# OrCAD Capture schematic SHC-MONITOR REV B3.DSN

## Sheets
1 01 Title Page: title: Monitor; rev: C; company: Freescale Semiconductor; note: SCH-MONITOR PDF: SPF-MONITOR; note: 6501 William Cannon Drive West; note: Austin, TX 78735-8598
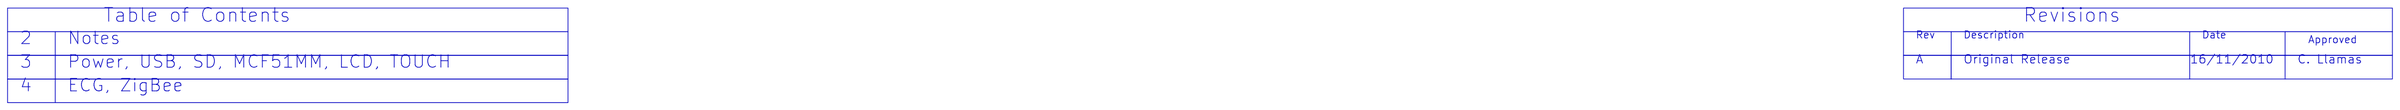
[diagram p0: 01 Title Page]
2 02 Notes: note: SCH-XXXXX PDF: SPF-XXXXX
3 03 Power, MCF51MM, USB, SD, LCD: size C; note: SCH-XXXXX PDF: SPF-XXXXX
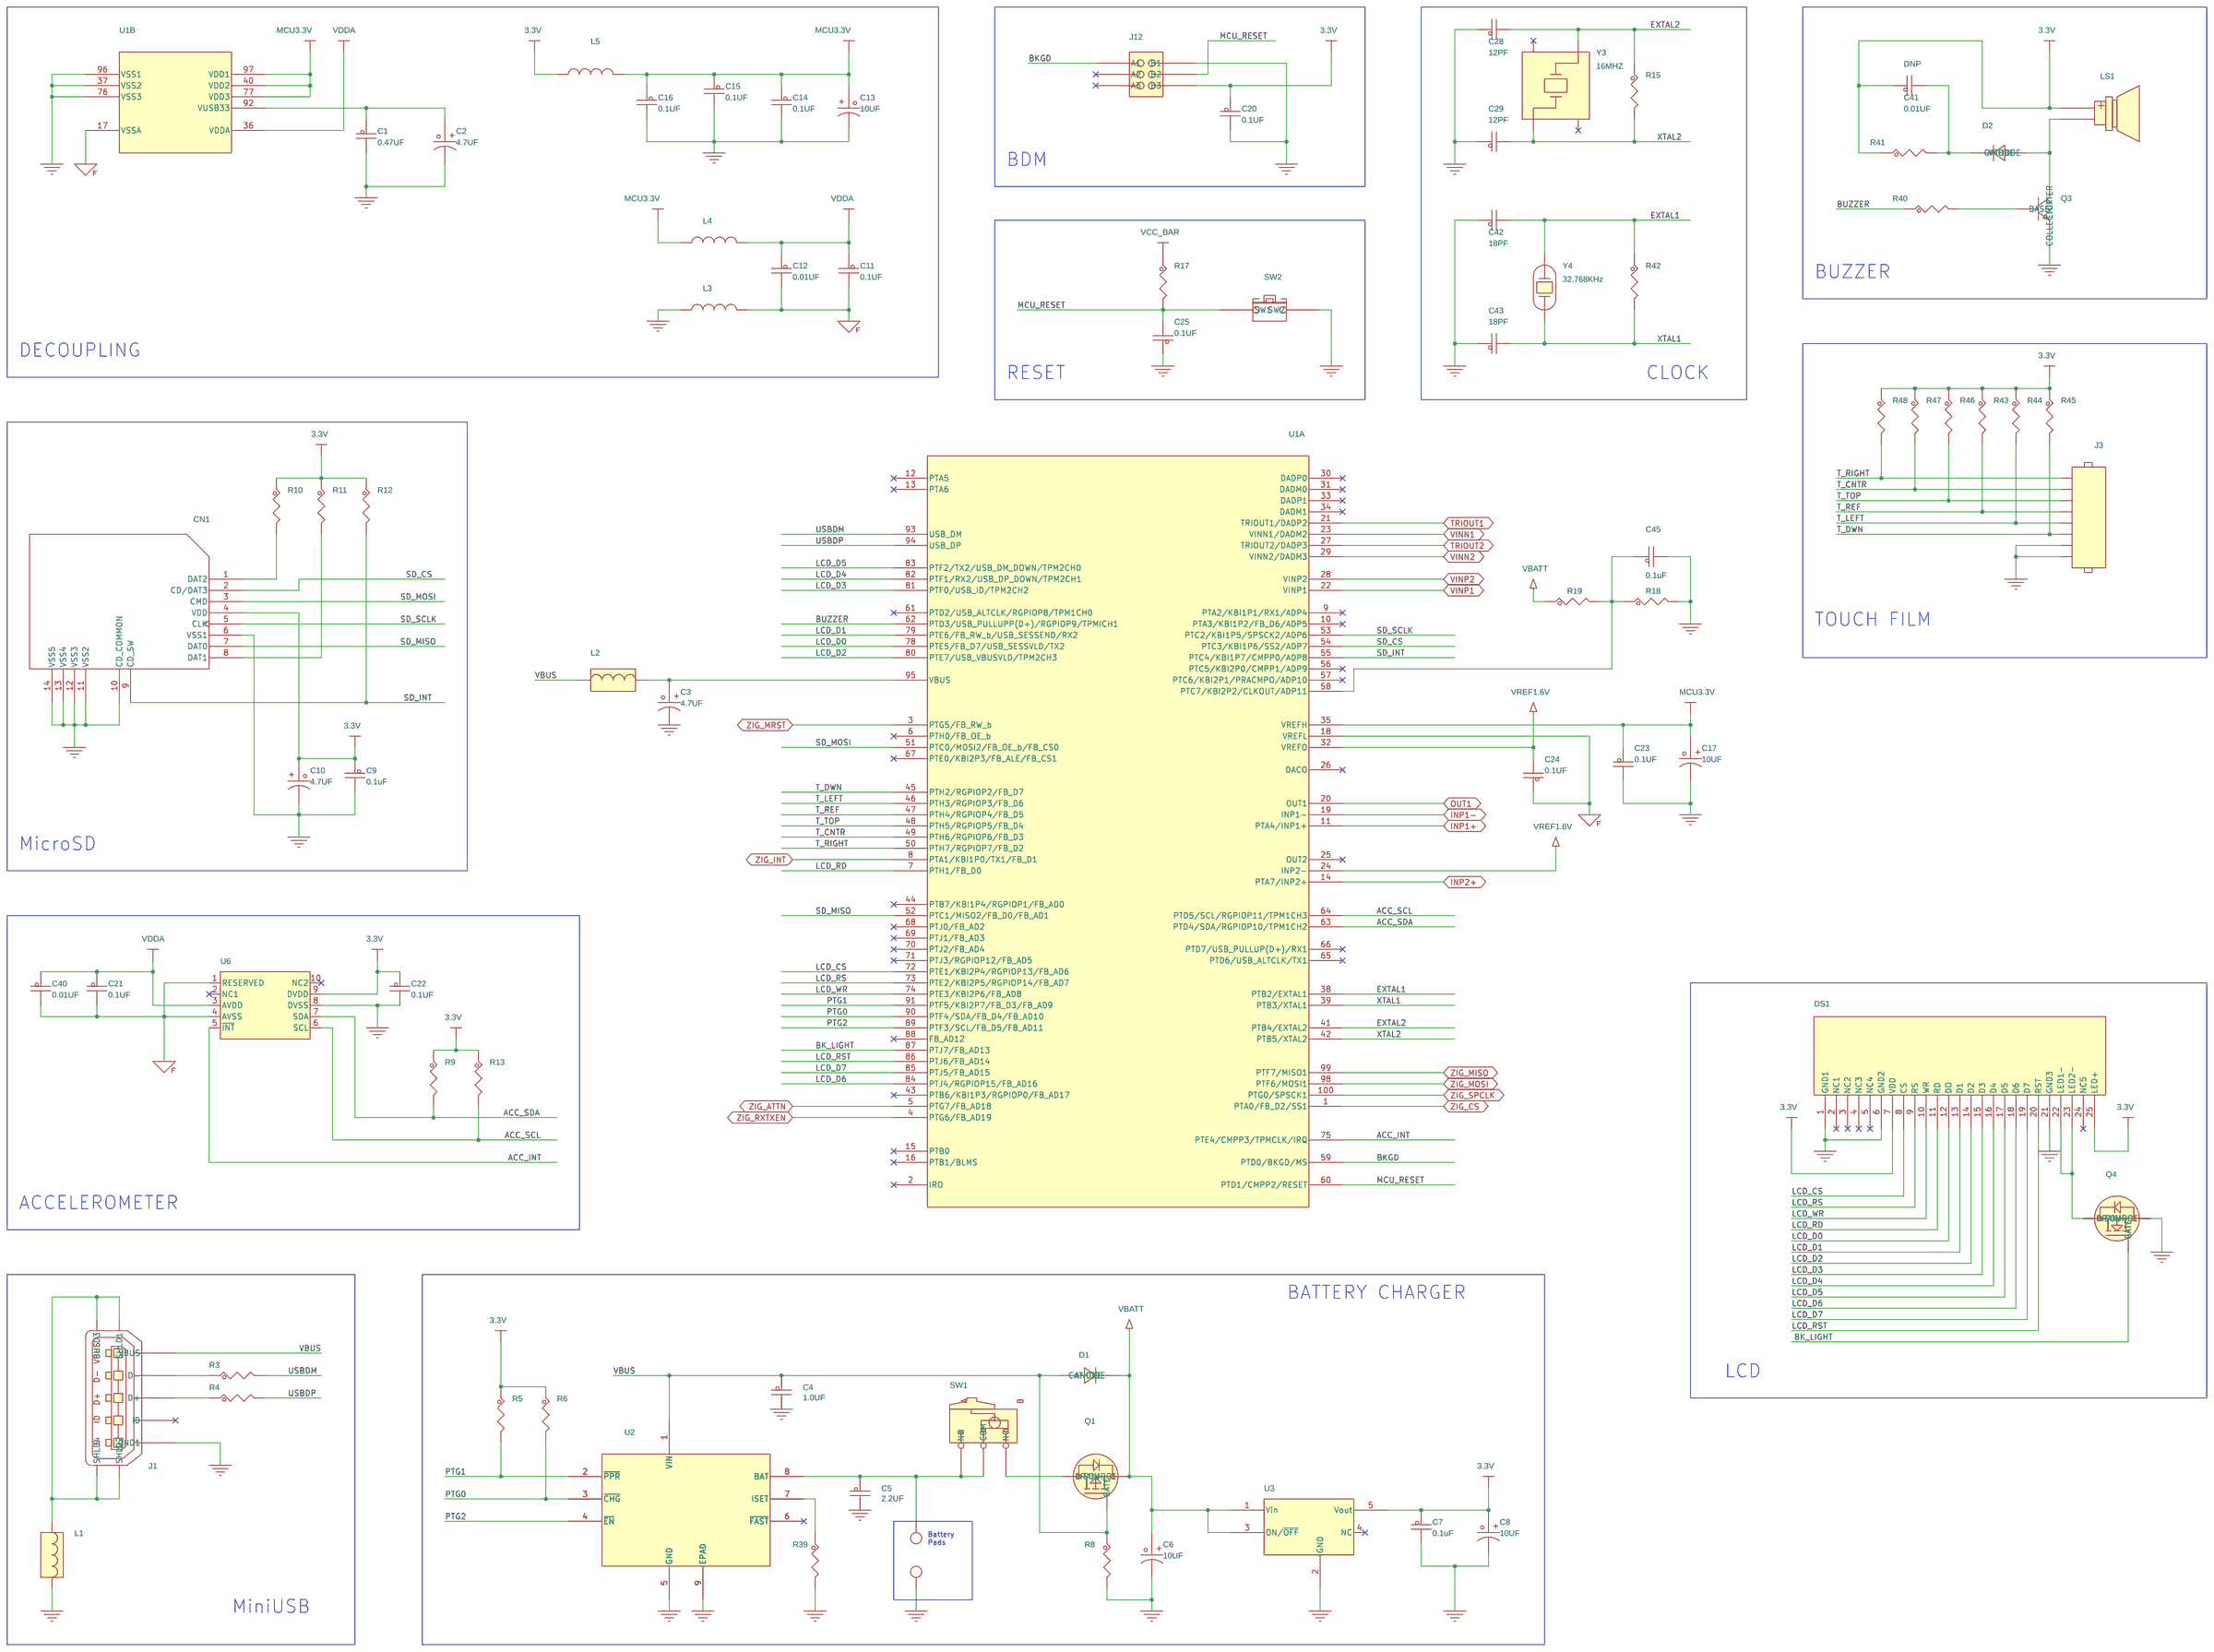
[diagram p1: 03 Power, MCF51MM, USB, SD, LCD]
4 04 ECG, Zigbee: size C; title: MONITOR; note: SCH-XXXXX PDF: SPF-XXXXX
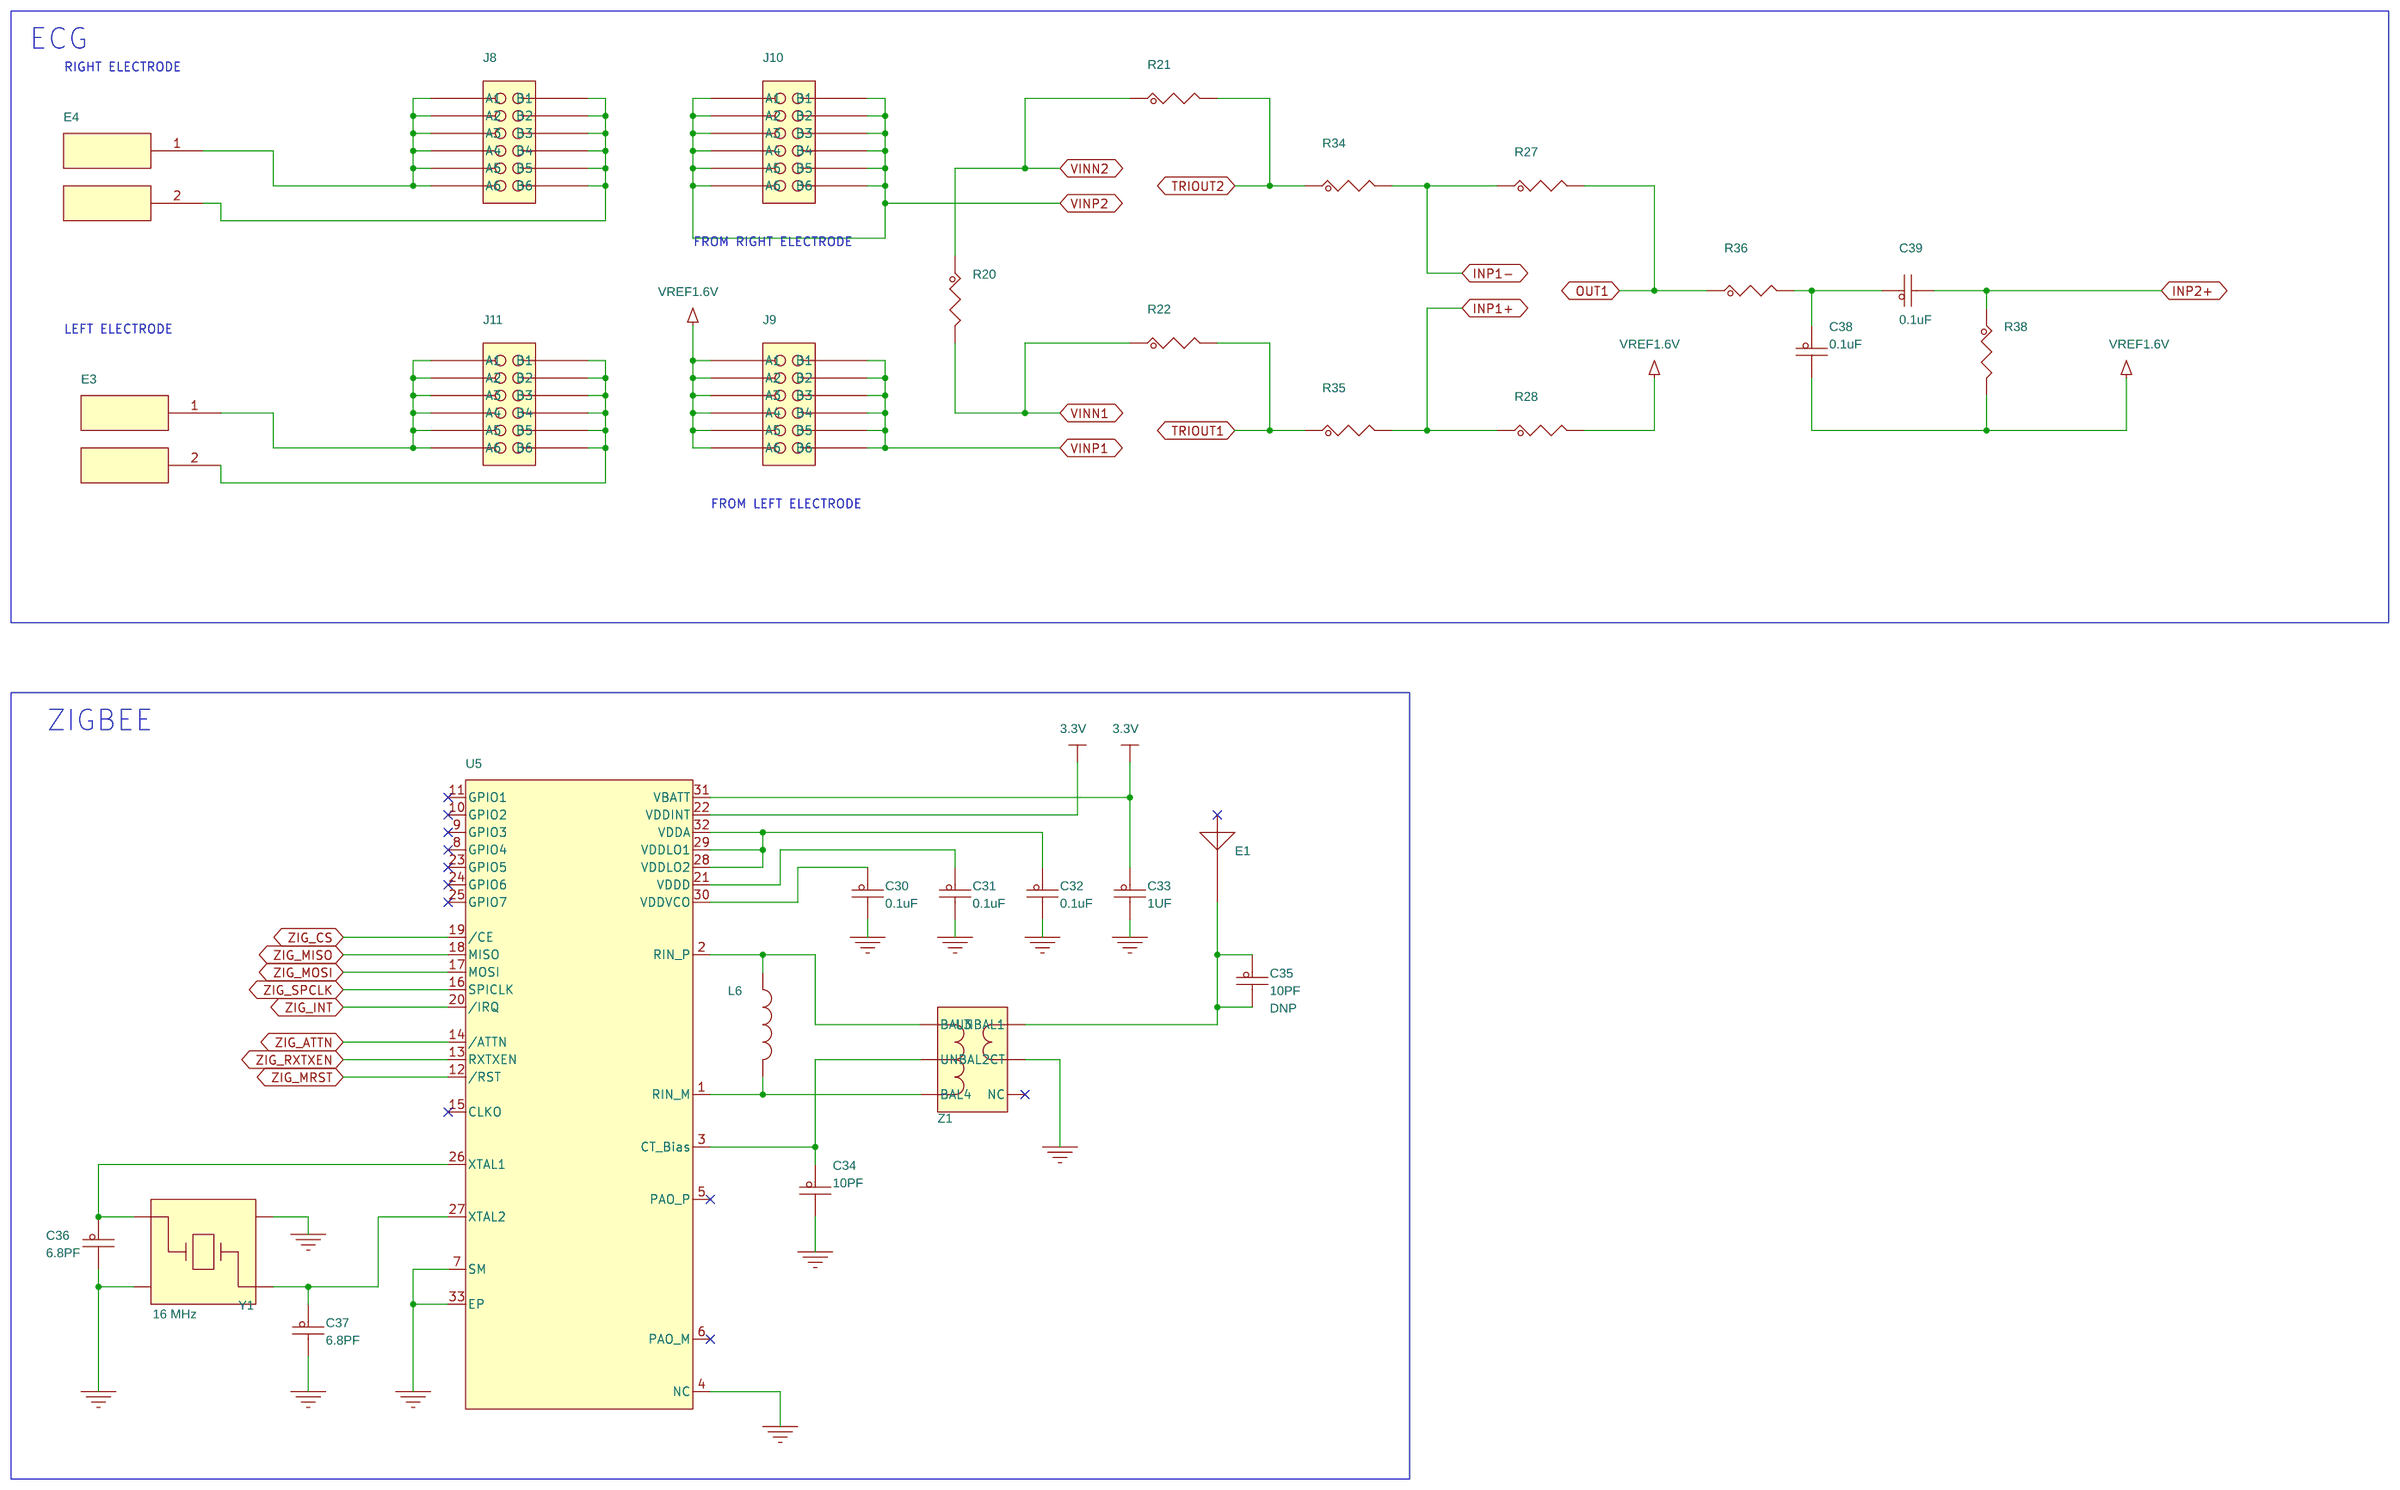
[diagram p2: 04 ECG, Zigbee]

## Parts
sheet 03 Power, MCF51MM, USB, SD, LCD
C1  0.47UF  [CC0402_25]
C2  4.7UF  [CC3528-21]
C3  4.7UF  [CC3528-21]
C4  1.0UF  [CC0402_25]
C5  2.2UF  [CC0402_25]
C6  10UF  [CC3216]
C7  0.1uF  [CC0402_25]
C8  10UF  [CC3216]
C9  0.1uF  [CC0402_25]
C10  4.7UF  [CC3528-21]
C11  0.1UF  [CC0402_25]
C12  0.01UF  [CC0402_25]
C13  10UF  [CC3216]
C14  0.1UF  [CC0402_25]
C15  0.1UF  [CC0402_25]
C16  0.1UF  [CC0402_25]
C17  10UF  [CC3216]
C20  0.1UF  [CC0402_25]
C21  0.1UF  [CC0402_25]
C22  0.1UF  [CC0402_25]
C23  0.1UF  [CC0402_25]
C24  0.1UF  [CC0402_25]
C25  0.1UF  [CC0402_25]
C28  12PF  [CC0402_25]
C29  12PF  [CC0402_25]
C40  0.01UF  [CC0402_25]
C41  0.01UF  [CC0402_25]
C42  18PF  [CC0402_25]
C43  18PF  [CC0402_25]
C45  0.1uF  [CC0805_OV]
CN1  Conn MicroSD  [CON_SDCARD_8F_SM_RA]
D1  FM4001  [DO214AC_AK]
D2  FM4001  [DO214AC_AK]
DS1  NHD-1.8-128160ZF-CTXL#  [lcdmodule_25p_0p8_34x47_smt]
J1  USB-MiniB  [con5_musb_b_skt_ra_sm]
J3  08FFS-SP-TF  [con_ffs_8f_50_sm_ra]
J12  HDR_2X3  [HDR203]
L1  26OHM  [IND_1206A]
L2  26OHM  [IND_1206A]
L3  100MHZ  [IND_0603]
L4  100MHZ  [IND_0603]
L5  100MHZ  [IND_0603]
LS1  CSQG703BP  [buzzer_6p5_12x3p8_th]
Q1  ZXM61P02F  [sot23-40x40]
Q3  MMBT5179  [sot-23]
Q4  BSH103  [sot23]
R3  33  [RC0402_25]
R4  33  [RC0402_25]
R5  4.7K  [RC0402_25]
R6  4.7K  [RC0402_25]
R8  1K  [RC0402_25]
R9  4.7K  [RC0402_25]
R10  10K  [RC0402_25]
R11  10K  [RC0402_25]
R12  10K  [RC0402_25]
R13  4.7K  [RC0402_25]
R15  1M  [RC0402_25]
R17  4.7K  [RC0402_25]
R18  1M  [RC0402_25]
R19  1M  [RC0402_25]
R39  10K  [RC0402_25]
R40  470  [RC0402_25]
R41  0  [RC0402_25]
R42  1M  [RC0402_25]
R43  1M  [RC0402_25]
R44  1M  [RC0402_25]
R45  1M  [RC0402_25]
R46  1M  [RC0402_25]
R47  1M  [RC0402_25]
R48  1M  [RC0402_25]
SW1  JS102011SAQN  [sw3_spdt_ra_sm]
SW2  SW2_STM151XX  [sw2_4x3mm_sm]
TP29  TPAD_030  [TPAD_030]
TP30  TPAD_030  [TPAD_030]
U1  MCF51MM256  [lqfp100_0p5_14x14]  (sections A,B)
U2  MC34673AEP  [dfn_8_0p5_2x3]
U3  LP2981IM5X3.3/NOPB  [sot-23-5]
U6  MMA7660FC  [dfn_10_0p5_3x3a]
Y3  16MHZ  [xtlosc4_3p2x2p5mm_sm]
Y4  32.768KHz  [xtl2_4p2x1p6]
sheet 04 ECG, Zigbee
C30  0.1uF  [CC0402_25]
C31  0.1uF  [CC0402_25]
C32  0.1uF  [CC0402_25]
C33  1UF  [CC0402_25]
C34  10PF  [CC0402_25]
C35  10PF  [CC0402_25]
C36  6.8PF  [CC0402_25]
C37  6.8PF  [CC0402_25]
C38  0.1uF  [CC0402_25]
C39  0.1uF  [CC0402_25]
E1  ANTENNA_2400MHZ  [antenna-2450]
E3  ELECTRODE  [electrode2_rec_760x360]
E4  ELECTRODE  [electrode2_rec_760x360]
J8  CON SKT 12  [con2x6_100_sm]
J9  CON PLUG 12  [con2x6_100_ra_sm]
J10  CON PLUG 12  [con2x6_100_ra_sm]
J11  CON SKT 12  [con2x6_100_sm]
L6  4.7nH  [IND_0402]
R20  1M  [RC0402_25]
R21  10K  [RC0402_25]
R22  10K  [RC0402_25]
R27  100K  [RC0402_25]
R28  100K  [RC0402_25]
R34  3.3K  [RC0402_25]
R35  3.3K  [RC0402_25]
R36  33K  [RC0402_25]
R38  1M  [RC0402_25]
U5  MC13202FC  [QFN32_MC1320X]
Y1  16 MHz  [xtlosc4_2p6x2p1mm_sm]
Z1  50/200 OHMS  [xfmr6_0p65_2x1]

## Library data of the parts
C1 = CAP_NP: CAP CER 0.47UF 6.3V 10% X5R 0402; AGILE_PN: 150-77952; CAD_APPROVED: Yes; FPLIST: CC0402_25,CC0402_HD,0402_CC; HEIGHT: 0.55MM; MFG_NAME01: Murata; MFG_PN01: GRM155R60J474KE19D; ROHS: Yes; Tolerance: 10%
C2 C3 C10 = CAP_POL: CAP TANT 4.7UF 25V 20% -- 3528-21; AGILE_PN: 150-75264; CAD_APPROVED: YES; HEIGHT: 2.1 MM; MFG_NAME01: KEMET; MFG_PN01: T491B475M025AT; ROHS: Yes; Tolerance: 20%
C4 = CAP_NP: CAP CER 1.0UF 6.3V 20% X5R 0402; AGILE_PN: 150-75919; CAD_APPROVED: Yes; FPLIST: CC0402_25,CC0402_HD,0402_CC; HEIGHT: 0.55 MM; MFG_NAME01: TDK; MFG_PN01: C1005X5R0J105M; ROHS: Yes; Tolerance: 20%
C5 = CAP_NP: CAP CER 2.2UF 6.3V 20% X5R 0402; AGILE_PN: 150-76792; CAD_APPROVED: Yes; FPLIST: CC0402_25,CC0402_HD,0402_CC; HEIGHT: 0.55MM; MFG_NAME01: KEMET; MFG_PN01: C0402C225M9PACTU; ROHS: Yes; Tolerance: 20%
C6 C8 C13 C17 = CAP_POL: CAP TANT 10UF 6.3V 10% -- 3216-18; AGILE_PN: 150-75288; CAD_APPROVED: YES; HEIGHT: 1.8MM; MFG_NAME01: AVX; MFG_PN01: TAJA106K006RNJ; ROHS: Yes; Tolerance: 10%
C7 C9 = CAP_NP: CAP CER 0.1UF 10V 10% X7R 0402; AGILE_PN: 150-30217; CAD_APPROVED: Yes; FPLIST: CC0402_25,CC0402_HD,CC0402_SQ,0402_CC; HEIGHT: 0.55 MM; MFG_NAME01: SMEC; MFG_PN01: MCCB104K0NRTF; ROHS: Yes
C11 C14-C16 C20-C25 = CAP_NP: CAP CER 0.1UF 10V 10% X5R 0402; AGILE_PN: 150-75634; CAD_APPROVED: Yes; FPLIST: CC0402_25,CC0402_HD,0402_CC; HEIGHT: 0.64MM; MFG_NAME01: KEMET; MFG_PN01: C0402C104K8PAC; ROHS: Yes; Tolerance: 10%
C12 = CAP_NP: CAP CER 0.01UF 16V 20% X7R 0402; AGILE_PN: 150-30082; CAD_APPROVED: Yes; FPLIST: CC0402_25,CC0402_HD,0402_CC; HEIGHT: 0.56MM; MFG_NAME01: AVX; MFG_PN01: 0402YC103MAT2A; ROHS: Yes; Tolerance: 20%
C28 C29 = CAP_NP: CAP CER 12PF 50V 5% C0G 0402; AGILE_PN: 150-75680; CAD_APPROVED: Yes; FPLIST: CC0402_25,CC0402_HD,0402_CC; HEIGHT: 0.55MM; MFG_NAME01: MURATA; MFG_PN01: GRM1555C1H120JZ01D; ROHS: Yes; Tolerance: 5%
C40 = CAP_NP: CAP CER 0.01UF 10V 20% X7R 0402; AGILE_PN: 150-30081; CAD_APPROVED: Yes; FPLIST: CC0402_25,CC0402_HD,0402_CC; HEIGHT: 0.4MM; MFG_NAME01: AVX; MFG_PN01: 0402ZC103MAT2A; ROHS: Yes; Tolerance: 20%
C41 = CAP_NP: CAP CER 0.01UF 16V 20% X7R 0402; AGILE_PN: 150-30082; ASSY_OPT: DNP; CAD_APPROVED: Yes; FPLIST: CC0402_25,CC0402_HD,0402_CC; HEIGHT: 0.56MM; MFG_NAME01: AVX; MFG_PN01: 0402YC103MAT2A; ROHS: Yes; Tolerance: 20%
C42 C43 = CAP_NP: CAP CER 18PF 50V 1% C0G 0402; AGILE_PN: 150-76630; CAD_APPROVED: Yes; FPLIST: CC0402_25,CC0402_HD,0402_CC; HEIGHT: 0.59MM; MFG_NAME01: CAPAX TECHNOLOGIES INC.; MFG_PN01: 0402G180F500SNT; ROHS: Yes; Tolerance: 1%
C45 = CAP_NP: CAP CER 0.1UF 100V 10% X7R 0805; AGILE_PN: 150-78700; CAD_APPROVED: Yes; FPLIST: CC0805_OV,CC0805,0805_CC; HEIGHT: 1.4MM; MFG_NAME01: MURATA; MFG_PN01: GCM21BR72A104KA37L; ROHS: Yes; Tolerance: 10%
CN1 = CONN_MICRO_SD_CARD_REVERSED: CON MICRO_SD 1.1MM 1.8MM -- Reverse Mount; AGILE_PN: 211-78813; CAD_APPROVED: Yes; HEIGHT: 1.95 MM; MFG_NAME01: Molex; MFG_PN01: 5027740891; ROHS: Yes
D1 D2 = 3A_20V_SS32: DIODE RECT 1.0A 50V DO-214AC; AGILE_PN: 480-30046; CAD_APPROVED: Yes; HEIGHT: 2.31 MM; MFG_NAME01: RECTRON; ROHS: Yes
DS1 = LCDMODULE_NHD_25P: TFT LCD DISPLAY MODULE WHT 25.5MA SMT; AGILE_PN: TMP-WF-14523; CAD_APPROVED: Yes; HEIGHT: 2.7MM; MFG_NAME01: NEWHAVEN DISPLAY INTERNATIONAL; MFG_PN01: NDH-1.8-128160ZF-CTXL#; ROHS: Yes
J1 = USB_MINI_B_SKT: CON 5 USB2.0 MINI-B RA SHLD SKT SMT 0.8MM SP AU; AGILE_PN: 211-77302; CAD_APPROVED: Yes; HEIGHT: 3.95MM; MFG_NAME01: HIROSE; MFG_PN01: UX60A-MB-5ST; ROHS: Yes
J3 = HDR_1X8_M: CON 1X8 FFS RA SMT 1.25MM SP 3.2MM -- TOP CONTACT; AGILE_PN: 211-78790; CAD_APPROVED: Yes; HEIGHT: 3.2 MM; MFG_NAME01: JST MFG. CO; MFG_PN01: 08FFS-SP-TF(LF)(SN); ROHS: Yes
J12 = CONN_HDR_3X2: HDR 2X3 TH 100MIL CTR 330H SN 115L; AGILE_PN: 210-79360; CAD_APPROVED: Yes; HEIGHT: 8.58MM; MFG_NAME01: Samtec; MFG_PN01: TSW-103-23-T-D; ROHS: Yes
L1 L2 = BEAD: IND FER BEAD 26 OHM@100MHZ 1.5A 25% 1206; AGILE_PN: 180-75060; CAD_APPROVED: Yes; FPLIST: IND_1206A,1206_CC; HEIGHT: 1.3MM; MFG_NAME01: LAIRD TECHNOLOGIES; MFG_PN01: MI1206K260R-10; PART_TYPE: FERRITE; ROHS: Yes; Tolerance: 25%
L3-L5 = IND: IND FER BEAD 100 OHM@100MHZ 1A 25% 0603; AGILE_PN: 180-75495; CAD_APPROVED: Yes; FPLIST: IND_0603,0603_CC; HEIGHT: 0.8MM; MFG_NAME01: TDK; MFG_PN01: MPZ1608D101B; PART_TYPE: Inductor; ROHS: Yes
LS1 = SPEAKER: BUZZER MAG 2.0KHZ 3V 12MM TH; AGILE_PN: 510-75579; CAD_APPROVED: Yes; HEIGHT: 4.3MM; MFG_NAME01: CUI STACK; ROHS: Yes
Q1 = MOSFET_P: TRAN PMOS SW 20VDS SOT23; AGILE_PN: 480-76217; CAD_APPROVED: Yes; HEIGHT: 1.1MM; MFG_NAME01: ZETEX INC; MFG_PN01: ZXM61P02F_; ROHS: Yes
Q3 = NPN: TRAN NPN RF 12V 0.05A SOT23; AGILE_PN: 480-78147; CAD_APPROVED: Yes; HEIGHT: 1.09MM; MFG_NAME01: Fairchild; ROHS: Yes
Q4 = MOSFET_N: TRAN NMOS SW 30VDS SOT-23; AGILE_PN: 480-75778; CAD_APPROVED: Yes; HEIGHT: 1.1MM; MFG_NAME01: PHILIPS SEMICONDUCTOR; ROHS: Yes
R3 R4 = RES: RES MF 33 OHM 1/16W 5% 0402; AGILE_PN: 470-75634; CAD_APPROVED: Yes; FPLIST: RC0402_25,RC0402_HD,0402_CC; MFG_NAME01: SMEC; MFG_PN01: RC73L2Z330JTF; ROHS: Yes; Tolerance: 5%
R5 R6 R9 R13 R17 = RES: RES MF 4.7K 1/16W 5% 0402; AGILE_PN: 470-75626; CAD_APPROVED: Yes; FPLIST: RC0402_25,RC0402_HD,0402_CC; MFG_NAME01: YAGEO AMERICA; MFG_PN01: RC0402JR-074K7L; ROHS: Yes; Tolerance: 5%
R8 = RES: RES MF 1.0K 1/16W 5% 0402; AGILE_PN: 470-75555; CAD_APPROVED: Yes; FPLIST: RC0402_25,RC0402_HD,RC0402_X2,0402_CC; MFG_NAME01: VISHAY INTERTECHNOLOGY; MFG_PN01: CRCW04021K00JNED; ROHS: Yes; Tolerance: 5%
R10-R12 R21 R22 R39 = RES: RES MF 10K 1/16W 5% 0402; AGILE_PN: 470-75557; CAD_APPROVED: Yes; FPLIST: RC0402_25,RC0402_HD,0402_CC; MFG_NAME01: VISHAY INTERTECHNOLOGY; MFG_PN01: CRCW040210K0JNED; ROHS: Yes; Tolerance: 5%
R15 R18 R19 R38 = RES: RES MF 1.0M 1/16W 1% 0402; AGILE_PN: 470-30000; CAD_APPROVED: Yes; FPLIST: RC0402_25,RC0402_HD,0402_CC; MFG_NAME01: VISHAY INTERTECHNOLOGY; MFG_PN01: CRCW04021M00FKED; ROHS: Yes; Tolerance: 1%
R40 = RES: RES TF 470 1/16W 5% RC0402; AGILE_PN: 470-76556; CAD_APPROVED: Yes; FPLIST: RC0402_25,RC0402_HD,0402_CC; MFG_NAME01: BOURNS; MFG_PN01: CR0402JW471GLF; ROHS: Yes; Tolerance: 5%
R41 = RES: RES MF ZERO OHM 1/16W 5% 0402; AGILE_PN: 470-75394; CAD_APPROVED: Yes; FPLIST: RC0402_25,RC0402_HD,RC0402_X2,0402_CC; MFG_NAME01: ROHM; MFG_PN01: MCR01MZPJ000; ROHS: Yes; Tolerance: 5%
R20 R42-R48 = RES: RES MF 1.0M 1/10W 5% 0402; AGILE_PN: 470-79978; CAD_APPROVED: Yes; FPLIST: RC0402_25,RC0402_HD,0402_CC; MFG_NAME01: PANASONIC; MFG_PN01: ERJ-2GEJ105X; ROHS: Yes; Tolerance: 5%
SW1 = SW3_SPDT_SLIDE: SW SPDT RA SLD 6V 300MA SMT; AGILE_PN: 510-76978; CAD_APPROVED: Yes; HEIGHT: 3.5MM; MFG_NAME01: C&K COMPONENTS; ROHS: Yes
SW2 = SW2_STM151XX: SW SPST MOM NO TACT 12V 50MA SMT; AGILE_PN: 510-76958; CAD_APPROVED: Yes; HEIGHT: 2MM; MFG_NAME01: E SWITCH; MFG_PN01: TL1015BF160QG; ROHS: Yes
TP29 TP30 = TestLoop: TEST POINT PAD 30MIL DIA SMT, NO PART TO ORDER; AGILE_PN: 211-76642; CAD_APPROVED: Yes; HEIGHT: 0.1MM; MFG_NAME01: NOTACOMPONENT; MFG_PN01: NOTACOMPONENT; ROHS: Yes
U1 = MCF51MM256: IC MCU 32BIT 256K FLASH 32K RAM 1.8-3.6V LQFP100; AGILE_PN: 344-01044; CAD_APPROVED: Yes; HEIGHT: 1.7MM; MFG_NAME01: FREESCALE SEMICONDUCTOR; MFG_PN01: MCF51MM256CLL; ROHS: Yes
U2 = MC34673AEP: IC CHARGER LI-ION/POLYMER BATT 1.2A 20V 8-UDFN; AGILE_PN: 315-76709; CAD_APPROVED: Yes; HEIGHT: 0.65MM; MFG_NAME01: FREESCALE SEMICONDUCTOR; ROHS: Yes
U3 = LP2980_M5: IC VREG LDO MICROPOWER 3.3V 100MA 2.1-16V SOT23-5; AGILE_PN: 315-77811; CAD_APPROVED: Yes; HEIGHT: 1.22MM; MFG_NAME01: NATIONAL SEMICONDUCTOR; MFG_PN01: LP2981IM5X-3.3/NOPB; ROHS: Yes
U6 = MMA7660FC: IC SENSOR ACCELEROMETER 2.4-3.6V DFN10; AGILE_PN: 312-79438; CAD_APPROVED: Yes; HEIGHT: 1MM; MFG_NAME01: FREESCALE SEMICONDUCTOR; ROHS: Yes
Y3 = XTAL_0: XTAL 16MHZ FIXED -- SMT 3.2X2.5MM; AGILE_PN: 230-75677; CAD_APPROVED: Yes; HEIGHT: 0.7MM; MFG_NAME01: NDK; MFG_PN01: NX3225SA-16.000000MHZ; ROHS: Yes
Y4 = XTAL: XTAL 32.768KHZ -- -- SMD; AGILE_PN: 230-77492; CAD_APPROVED: Yes; HEIGHT: 0.9MM; MFG_NAME01: SARONIX; MFG_PN01: G73270001; ROHS: Yes
C30-C32 = CAP_NP: CAP CER 0.1UF 16V 10% X5R 0402; AGILE_PN: 150-75663; CAD_APPROVED: Yes; FPLIST: CC0402_25,CC0402_HD,0402_CC; HEIGHT: 0.55MM; MFG_NAME01: TDK; MFG_PN01: C1005X5R1C104K; ROHS: Yes; Tolerance: 10%
C33 = CAP_NP: CAP CER 1UF 6.3V 10% X5R 0402; AGILE_PN: 150-76275; CAD_APPROVED: Yes; FPLIST: CC0402_25,CC0402_HD,0402_CC; HEIGHT: 0.55MM; MFG_NAME01: KEMET; MFG_PN01: C0402C105K9PAC; ROHS: Yes; Tolerance: 10%
C34 = CAP_NP: CAP CER 10PF 50V +/-0.25PF C0G 0402; AGILE_PN: 150-30284; CAD_APPROVED: Yes; FPLIST: CC0402_25,CC0402_HD,0402_CC; HEIGHT: 0.55MM; MFG_NAME01: SAMSUNG; MFG_PN01: CL05C100CB5NNNC; ROHS: Yes; Tolerance: +/-0.25PF
C35 = CAP_NP: CAP CER 10PF 16V 0.25PF C0G 0402; AGILE_PN: 150-75722; ASSY_OPT: DNP; CAD_APPROVED: Yes; FPLIST: CC0402_25,CC0402_HD,0402_CC; HEIGHT: 0.55MM; MFG_NAME01: SAMSUNG; MFG_PN01: CL05C100CO5NNNC; ROHS: Yes; Tolerance: 0.25PF
C36 C37 = CAP_NP: CAP CER 6.8PF 50V 0.5PF C0G 0402; AGILE_PN: 150-30300; CAD_APPROVED: Yes; FPLIST: CC0402_25,CC0402_HD,0402_CC; HEIGHT: 0.55MM; MFG_NAME01: MURATA; MFG_PN01: GRM1555C1H6R8DZ01J; ROHS: Yes; Tolerance: 0.5PF %
C38 C39 = CAP_NP: CAP CER 0.1UF 25V 10% X5R 0402; AGILE_PN: 150-78633; CAD_APPROVED: Yes; FPLIST: CC0402_25,CC0402_HD,0402_CC; HEIGHT: 0.55MM; MFG_NAME01: YAGEO AMERICA; MFG_PN01: CC0402KRX5R8BB104; ROHS: Yes; Tolerance: 10%
E1 = ANTENNA_2P4GHZ: ANTENNA 2.4GHZ SMT 5.0X2.0X1.1; AGILE_PN: 510-75919; CAD_APPROVED: Yes; HEIGHT: 1.3MM; MFG_NAME01: JOHANSON TECHNOLOGY; MFG_PN01: 2450AT42A100; ROHS: Yes
E3 E4 = ELECTRODE_B: ELECTRODE 2 PIN 760 x 360 NO PART TO ORDER; AGILE_PN: TMP-WF-15267; CAD_APPROVED: Yes; HEIGHT: 0.127MM; MFG_NAME01: N/A; PRE_APN: 510-77804; ROHS: Yes
J8 J11 = CONN_HDR_6X2: CON 2X6 SKT SMT 2.54MM SP 254H AU; AGILE_PN: TMP-WF-14216; CAD_APPROVED: Yes; HEIGHT: 6.45 MM; MFG_NAME01: 3M; MFG_PN01: 966212-2000-AR-PR; PRE_APN: 211-79027; ROHS: Yes
J9 J10 = CONN_HDR_6X2: CON 2X6 PLUG RA SMT 2.54MM SP 256H AU; AGILE_PN: TMP-WF-14218; CAD_APPROVED: Yes; HEIGHT: 6.5 MM; MFG_NAME01: 3M; MFG_PN01: 961212-5900-AR-PR; PRE_APN: 211-79028; ROHS: Yes
L6 = INDUCTOR: IND -- 0.0047UH@100MHZ 400MA +/-0.3NF 0402; AGILE_PN: 180-75135; CAD_APPROVED: Yes; FPLIST: IND_0402,0402_CC; HEIGHT: 0.55MM; MFG_NAME01: TOKO INC.; MFG_PN01: LL1005-FHL4N7S; ROHS: Yes
R27 R28 = RES: RES MF 100K 1/16W 1% 0402; AGILE_PN: 470-76240; CAD_APPROVED: Yes; FPLIST: RC0402_25,RC0402_HD,0402_CC; MFG_NAME01: KOA SPEER; MFG_PN01: RK73H1ETTP1003F; ROHS: Yes; Tolerance: 1%
R34 R35 = RES: RES MF 3.3K 1/16W 5% 0402; AGILE_PN: 470-76064; CAD_APPROVED: Yes; FPLIST: RC0402_25,RC0402_HD,0402_CC; MFG_NAME01: VISHAY INTERTECHNOLOGY; MFG_PN01: CRCW04023K30JNED; ROHS: Yes; Tolerance: 5%
R36 = RES: RES MF 33K 1/16W 5% 0402; AGILE_PN: 470-75615; CAD_APPROVED: Yes; FPLIST: RC0402_25,RC0402_HD,0402_CC; MFG_NAME01: SMEC; MFG_PN01: RC73L2Z333JTF; ROHS: Yes; Tolerance: 5%
U5 = MC13202FC: IC XCVR 2.4GHZ 2/3.4V QFN32; AGILE_PN: 312-76396; CAD_APPROVED: Yes; HEIGHT: 1MM; MFG_NAME01: FREESCALE SEMICONDUCTOR; ROHS: Yes
Y1 = XTAL_0: XTAL 16MHZ -- 2520 SMD; AGILE_PN: 230-75774; CAD_APPROVED: Yes; HEIGHT: 0.55MM; MFG_NAME01: NDK; MFG_PN01: NX2520SA-16.000000MHz; ROHS: Yes
Z1 = LDB_21: XFMR BALUN 2.45GHZ +/-50MHZ 50/200OHM 3W SMT; AGILE_PN: 560-75413; CAD_APPROVED: Yes; FPLIST: xfmr6_0p65_2x1,XFMR_HHM1525_2x1_25mm_6P; HEIGHT: 0.95MM; MFG_NAME01: JOHANSON TECHNOLOGY; MFG_PN01: 2450BL15B200E; PART_TYPE: TRANSFORMERS; ROHS: Yes

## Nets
3.3V: C7.1 C8.1 C9.1 C10.1 C20.1 C22.1 C33.1 C41.1 CN1.4(VDD) DS1.7(VDD) DS1.25(LED+) J12.6(B3) L5.2 LS1.1 R5.1 R6.1 R9.1 R10.1 R11.1 R12.1 R13.1 R41.1 R43.1 R44.1 R45.1 R46.1 R47.1 R48.1 U3.5(Vout) U5.22(VDDINT) U5.31(VBATT) U6.9(DVDD)
GND: C1.2 C2.2 C3.2 C4.2 C5.2 C6.2 C7.2 C8.2 C9.2 C10.2 C13.2 C14.2 C15.2 C16.2 C17.2 C20.2 C22.2 C23.2 C25.1 C28.1 C29.1 C30.2 C31.2 C32.2 C33.2 C34.2 C36.2 C37.2 C42.1 C43.1 C45.2 CN1.6(VSS1) CN1.10(CD_COMMON) CN1.11(VSS2) CN1.12(VSS3) CN1.13(VSS4) CN1.14(VSS5) DS1.1(GND1) DS1.6(GND2) DS1.21(GND3) J1.5(GND1) J3.7 J3.8 J12.2(B1) L1.2 L3.2 Q3.2(EMITTER) Q4.2(SOURCE) R8.2 R18.2 R39.2 SW2.2(SW2) TP29.1(Pin1) U1.37(VSS2) U1.76(VSS3) U1.96(VSS1) U2.5(GND) U2.9(EPAD) U3.2(GND) U5.4(NC) U5.7(SM) U5.33(EP) U6.8(DVSS) Y1.2 Y1.4 Z1.5(CT)
GND_FIELD SIGNAL: C11.2 C12.2 C21.2 C24.1 C40.2 L3.1 U1.17(VSSA) U1.18(VREFL) U6.1(RESERVED) U6.4(AVSS)
VBATT: C6.1 D1.1(CATHODE) Q1.2(SOURCE) R19.1 U3.1(Vin) U3.3(ON/~{OFF})
VBUS: C4.1 D1.2(ANODE) J1.1(VBUS) L2.1 Q1.1(GATE) R8.1 U2.1(VIN)
VDDA: C11.1 C12.1 C21.1 C40.1 L4.1 U1.36(VDDA) U6.3(AVDD)
VINN1: R20.2 R22.1 U1.23(VINN1/DADM2)
VINN2: R20.1 R21.1 U1.29(VINN2/DADM3)
VINP1: J9.2(B1) J9.4(B2) J9.6(B3) J9.8(B4) J9.10(B5) J9.12(B6) U1.22(VINP1)
VINP2: J10.1(A1) J10.2(B1) J10.3(A2) J10.4(B2) J10.5(A3) J10.6(B3) J10.7(A4) J10.8(B4) J10.9(A5) J10.10(B5) J10.11(A6) J10.12(B6) U1.28(VINP2)
ACC_INT: U1.75(PTE4/CMPP3/TPMCLK/IRQ) U6.5(~{INT})
ACC_SCL: R13.2 U1.64(PTD5/SCL/RGPIOP11/TPM1CH3) U6.6(SCL)
ACC_SDA: R9.2 U1.63(PTD4/SDA/RGPIOP10/TPM1CH2) U6.7(SDA)
BK_LIGHT: Q4.1(GATE) U1.87(PTJ7/FB_AD13)
BKGD: J12.1(A1) U1.59(PTD0/BKGD/MS)
BUZZER: R40.1 U1.62(PTD3/USB_PULLUPP(D+)/RGPIOP9/TPMICH1)
EXTAL1: C42.2 R42.1 U1.38(PTB2/EXTAL1) Y4.2
EXTAL2: C28.2 R15.1 U1.41(PTB4/EXTAL2) Y3.3
INP1+: R28.1 R35.2 U1.11(PTA4/INP1+)
INP1-: R27.1 R34.2 U1.19(INP1-)
INP2+: C39.2 R38.1 U1.14(PTA7/INP2+)
LCD_CS: DS1.8(CS) U1.72(PTE1/KBI2P4/RGPIOP13/FB_AD6)
LCD_D0: DS1.12(DO) U1.78(PTE5/FB_D7/USB_SESSVLD/TX2)
LCD_D1: DS1.13(D1) U1.79(PTE6/FB_RW_b/USB_SESSEND/RX2)
LCD_D2: DS1.14(D2) U1.80(PTE7/USB_VBUSVLD/TPM2CH3)
LCD_D3: DS1.15(D3) U1.81(PTF0/USB_ID/TPM2CH2)
LCD_D4: DS1.16(D4) U1.82(PTF1/RX2/USB_DP_DOWN/TPM2CH1)
LCD_D5: DS1.17(D5) U1.83(PTF2/TX2/USB_DM_DOWN/TPM2CH0)
LCD_D6: DS1.18(D6) U1.84(PTJ4/RGPIOP15/FB_AD16)
LCD_D7: DS1.19(D7) U1.85(PTJ5/FB_AD15)
LCD_RD: DS1.11(RD) U1.7(PTH1/FB_D0)
LCD_RS: DS1.9(RS) U1.73(PTE2/KBI2P5/RGPIOP14/FB_AD7)
LCD_RST: DS1.20(RST) U1.86(PTJ6/FB_AD14)
LCD_WR: DS1.10(WR) U1.74(PTE3/KBI2P6/FB_AD8)
MCU3.3V: C13.1 C14.1 C15.1 C16.1 C17.1 C23.1 L4.2 L5.1 R17.1 U1.35(VREFH) U1.40(VDD2) U1.77(VDD3) U1.97(VDD1)
MCU_RESET: C25.2 J12.4(B2) R17.2 SW2.1(SW1) U1.60(PTD1/CMPP2/RESET)
OUT1: R27.2 R36.1 U1.20(OUT1)
PTG0: R6.2 U1.90(PTF4/SDA/FB_D4/FB_AD10) U2.3(~{CHG})
PTG1: R5.2 U1.91(PTF5/KBI2P7/FB_D3/FB_AD9) U2.2(~{PPR})
PTG2: U1.89(PTF3/SCL/FB_D5/FB_AD11) U2.4(~{EN})
SD_CS: CN1.2(CD/DAT3) U1.54(PTC3/KBI1P6/SS2/ADP7)
SD_INT: CN1.9(CD_SW) R12.2 U1.55(PTC4/KBI1P7/CMPP0/ADP8)
SD_MISO: CN1.7(DAT0) U1.52(PTC1/MISO2/FB_D0/FB_AD1)
SD_MOSI: CN1.3(CMD) U1.51(PTC0/MOSI2/FB_OE_b/FB_CS0)
SD_SCLK: CN1.5(CLK) U1.53(PTC2/KBI1P5/SPSCK2/ADP6)
T_CNTR: J3.2 R47.2 U1.49(PTH6/RGPIOP6/FB_D3)
T_DWN: J3.6 R45.2 U1.45(PTH2/RGPIOP2/FB_D7)
T_LEFT: J3.5 R44.2 U1.46(PTH3/RGPIOP3/FB_D6)
T_REF: J3.4 R43.2 U1.47(PTH4/RGPIOP4/FB_D5)
T_RIGHT: J3.1 R48.2 U1.50(PTH7/RGPIOP7/FB_D2)
T_TOP: J3.3 R46.2 U1.48(PTH5/RGPIOP5/FB_D4)
TRIOUT1: R22.2 R35.1 U1.21(TRIOUT1/DADP2)
TRIOUT2: R21.2 R34.1 U1.27(TRIOUT2/DADP3)
USBDM: R3.2 U1.93(USB_DM)
USBDP: R4.2 U1.94(USB_DP)
VREF1.6V: C24.2 C38.2 J9.1(A1) J9.3(A2) J9.5(A3) J9.7(A4) J9.9(A5) J9.11(A6) R28.2 R38.2 U1.24(INP2-) U1.32(VREFO)
XTAL1: C43.2 R42.2 U1.39(PTB3/XTAL1) Y4.1
XTAL2: C29.2 R15.2 U1.42(PTB5/XTAL2) Y3.1
ZIG_ATTN: U1.5(PTG7/FB_AD18) U5.14(/ATTN)
ZIG_CS: U1.1(PTA0/FB_D2/SS1) U5.19(/CE)
ZIG_INT: U1.8(PTA1/KBI1P0/TX1/FB_D1) U5.20(/IRQ)
ZIG_MISO: U1.99(PTF7/MISO1) U5.18(MISO)
ZIG_MOSI: U1.98(PTF6/MOSI1) U5.17(MOSI)
ZIG_MRST: U1.3(PTG5/FB_RW_b) U5.12(/RST)
ZIG_RXTXEN: U1.4(PTG6/FB_AD19) U5.13(RXTXEN)
ZIG_SPCLK: U1.100(PTG0/SPSCK1) U5.16(SPICLK)
N01665: Q1.3(DRAIN) SW1.1(NC)
N02698: J1.S1(SHLD1) J1.S2(SHLD2) J1.S3(SHLD3) J1.S4(SHLD4) L1.1
N02810: J1.2(D-) R3.1
N02910: C1.1 C2.1 U1.92(VUSB33)
N03154: C5.1 SW1.2(COM) SW1.3(NO) TP30.1(Pin1) U2.8(BAT)
N03295: R39.1 U2.7(ISET)
N04574: CN1.1(DAT2) R10.2
N04614: CN1.8(DAT1) R11.2
N25309: C45.1 R18.1 R19.2 U1.58(PTC7/KBI2P2/CLKOUT/ADP11)
N32500: C38.1 C39.1 R36.2
N41665: C30.1 U5.30(VDDVCO)
N41677: C31.1 U5.21(VDDD)
N41695: C32.1 U5.28(VDDLO2) U5.29(VDDLO1) U5.32(VDDA)
N42211: L6.1 U5.2(RIN_P) Z1.3(BAL3)
N42218: L6.2 U5.1(RIN_M) Z1.4(BAL4)
N42330: C34.1 U5.3(CT_Bias) Z1.2(UNBAL2)
N42476: C35.1 C35.2 E1.1 Z1.1(UNBAL1)
N42716: C36.1 U5.26(XTAL1) Y1.1
N42769: C37.1 U5.27(XTAL2) Y1.3
N99672: J1.3(D+) R4.1
N131191: Q3.1(BASE) R40.2
N131207: D2.2(ANODE) LS1.2 Q3.3(COLLECTOR)
N131223: C41.2 D2.1(CATHODE) R41.2
N132740: DS1.22(LED1-) DS1.23(LED2-) Q4.3(DRAIN)
N151371: C3.1 L2.2 U1.95(VBUS)
N217381: E4.1 J8.1(A1) J8.3(A2) J8.5(A3) J8.7(A4) J8.9(A5) J8.11(A6)
N217421: E4.2 J8.2(B1) J8.4(B2) J8.6(B3) J8.8(B4) J8.10(B5) J8.12(B6)
N217461: E3.1 J11.1(A1) J11.3(A2) J11.5(A3) J11.7(A4) J11.9(A5) J11.11(A6)
N217497: E3.2 J11.2(B1) J11.4(B2) J11.6(B3) J11.8(B4) J11.10(B5) J11.12(B6)

Not connected (* = marked no-connect by the designer): DS1 2(NC1)* 3(NC2)* 4(NC3)* 5(NC4)* 24(NC5)*; E1 2*; J1 4(ID)*; J12 3(A2)* 5(A3)*; U1 2(IRO)* 6(PTH0/FB_OE_b)* 9(PTA2/KBI1P1/RX1/ADP4)* 10(PTA3/KBI1P2/FB_D6/ADP5)* 12(PTA5)* 13(PTA6)* 15(PTB0)* 16(PTB1/BLMS)* 25(OUT2)* 26(DACO)* 30(DADP0)* 31(DADM0)* 33(DADP1)* 34(DADM1)* 43(PTB6/KBI1P3/RGPIOP0/FB_AD17)* 44(PTB7/KBI1P4/RGPIOP1/FB_AD0)* 56(PTC5/KBI2P0/CMPP1/ADP9)* 57(PTC6/KBI2P1/PRACMPO/ADP10)* 61(PTD2/USB_ALTCLK/RGPIOP8/TPM1CH0)* 65(PTD6/USB_ALTCLK/TX1)* 66(PTD7/USB_PULLUP(D+)/RX1)* 67(PTE0/KBI2P3/FB_ALE/FB_CS1)* 68(PTJ0/FB_AD2)* 69(PTJ1/FB_AD3)* 70(PTJ2/FB_AD4)* 71(PTJ3/RGPIOP12/FB_AD5)* 88(FB_AD12)*; U2 6(~{FAST})*; U3 4(NC)*; U5 5(PAO_P)* 6(PAO_M)* 8(GPIO4)* 9(GPIO3)* 10(GPIO2)* 11(GPIO1)* 15(CLKO)* 23(GPIO5)* 24(GPIO6)* 25(GPIO7)*; U6 2(NC1)* 10(NC2)*; Y3 2* 4*; Z1 6(NC)*

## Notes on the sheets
sheet 1
- Table of Contents
- Revisions
- 2
- Notes
- Rev
- Description
- Date
- Approved
- 3
- Power, USB, SD, MCF51MM, LCD, TOUCH
- A
- Original Release
- 16/11/2010
- C. Llamas
- 4
- ECG, ZigBee
sheet 3
- BDM
- BUZZER
- DECOUPLING
- RESET
- CLOCK
- TOUCH FILM
- MicroSD
- ACCELEROMETER
- BATTERY CHARGER
- LCD
- Battery
  Pads
- MiniUSB
sheet 4
- ECG
- RIGHT ELECTRODE
- FROM RIGHT ELECTRODE
- LEFT ELECTRODE
- FROM LEFT ELECTRODE
- ZIGBEE
